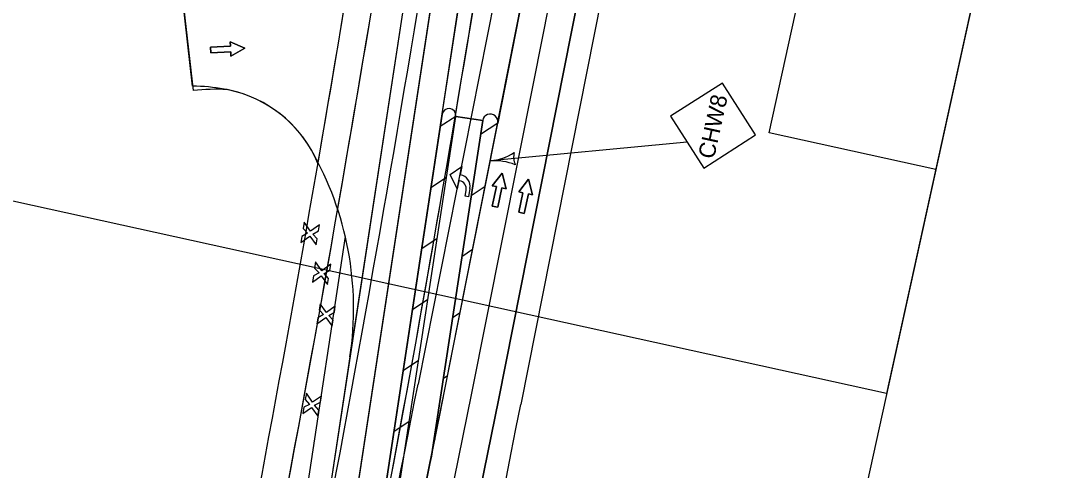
# Model space of a CAD drawing. Extents: x 14107086 to 14122011, y 8637163 to 8671583.
# Drawn here: x 14107764 to 14108216.1, y 8639702.8 to 8639900.3 of the extents above; entities that cross this region are included whole.
import ezdxf

# ---------------------------------------------------------------- set-up
doc = ezdxf.new("R2010")
doc.units = 0
for name, color, linetype in [('Cell', 7, 'Continuous'), ('dsn_stg_shd_prev', 7, 'Continuous'), ('dsnNonPlotable', 7, 'Continuous'), ('dsnPaintExistingChannelizingLaneYellow', 7, 'Continuous'), ('dsnPaintExistingEdgeLineRightWhite', 7, 'Continuous'), ('dsnPaintPlaceBrokenLaneWhite', 7, 'Continuous'), ('dsnPaintPlaceChannelizingLaneWhite', 7, 'Continuous'), ('dsnPaintPlaceChannelizingLaneYellow', 7, 'Continuous'), ('dsnPaintPlaceEdgeLineRightWhite', 7, 'Continuous'), ('dsnPaintRemoveDoubleCenterLineYellow', 7, 'Continuous'), ('dsnShadingPaved', 7, 'Continuous'), ('dsnStdLabel', 7, 'Continuous'), ('dsnTextOverlapEven', 7, 'Continuous'), ('Level 2', 7, 'Continuous'), ('Level 5', 7, 'Continuous')]:
    doc.layers.add(name, color=color, linetype=linetype)

msp = doc.modelspace()

# ---------------------------------------------------------------- linework, layer by layer
at = {"layer": 'Cell'}
for p, q in [((14107956.89, 8639829.91), (14107956.58, 8639829.95)), ((14107957.11, 8639832.53), (14107957.29, 8639832.5)), ((14107888.58, 8639811.69), (14107888.16, 8639808.97)), ((14107891.39, 8639807.83), (14107888.58, 8639811.69)), ((14107895.25, 8639810.65), (14107891.39, 8639807.83)), ((14107894.82, 8639807.93), (14107895.25, 8639810.65)), ((14107890.11, 8639806.9), (14107887.61, 8639805.52)), ((14107888.16, 8639808.97), (14107890.11, 8639806.9)), ((14107892.33, 8639806.55), (14107894.82, 8639807.93)), ((14107894.28, 8639804.47), (14107892.33, 8639806.55)), ((14107887.19, 8639802.8), (14107891.05, 8639805.61)), ((14107887.61, 8639805.52), (14107887.19, 8639802.8)), ((14107891.05, 8639805.61), (14107893.86, 8639801.76)), ((14107893.86, 8639801.76), (14107894.28, 8639804.47)), ((14107893.61, 8639794.31), (14107893.18, 8639791.59)), ((14107896.42, 8639790.45), (14107893.61, 8639794.31)), ((14107900.28, 8639793.26), (14107896.42, 8639790.45)), ((14107899.85, 8639790.55), (14107900.28, 8639793.26)), ((14107892.22, 8639785.42), (14107896.07, 8639788.23)), ((14107892.64, 8639788.13), (14107892.22, 8639785.42)), ((14107895.14, 8639789.51), (14107892.64, 8639788.13)), ((14107893.18, 8639791.59), (14107895.14, 8639789.51)), ((14107896.07, 8639788.23), (14107898.89, 8639784.37)), ((14107897.36, 8639789.16), (14107899.85, 8639790.55)), ((14107899.31, 8639787.09), (14107897.36, 8639789.16)), ((14107898.89, 8639784.37), (14107899.31, 8639787.09)), ((14107895.61, 8639775.98), (14107895.18, 8639773.26)), ((14107898.42, 8639772.12), (14107895.61, 8639775.98)), ((14107902.28, 8639774.93), (14107898.42, 8639772.12)), ((14107901.85, 8639772.22), (14107902.28, 8639774.93)), ((14107894.22, 8639767.09), (14107898.07, 8639769.9)), ((14107894.64, 8639769.8), (14107894.22, 8639767.09)), ((14107897.14, 8639771.18), (14107894.64, 8639769.8)), ((14107895.18, 8639773.26), (14107897.14, 8639771.18)), ((14107898.07, 8639769.9), (14107900.88, 8639766.04)), ((14107899.36, 8639770.84), (14107901.85, 8639772.22)), ((14107901.31, 8639768.76), (14107899.36, 8639770.84)), ((14107900.88, 8639766.04), (14107901.31, 8639768.76)), ((14107889.59, 8639736.62), (14107889.08, 8639733.92)), ((14107889.08, 8639733.92), (14107890.97, 8639731.78)), ((14107892.29, 8639732.68), (14107889.59, 8639736.62)), ((14107896.22, 8639735.38), (14107892.29, 8639732.68)), ((14107895.72, 8639732.68), (14107896.22, 8639735.38)), ((14107888.44, 8639730.48), (14107887.94, 8639727.77)), ((14107887.94, 8639727.77), (14107891.87, 8639730.47)), ((14107890.97, 8639731.78), (14107888.44, 8639730.48)), ((14107891.87, 8639730.47), (14107894.57, 8639726.54)), ((14107893.19, 8639731.37), (14107895.72, 8639732.68)), ((14107895.08, 8639729.24), (14107893.19, 8639731.37)), ((14107894.57, 8639726.54), (14107895.08, 8639729.24))]:
    msp.add_line(p, q, dxfattribs=at)
for points in [[(14107952.78, 8639832.67), (14107957.86, 8639836.14), (14107957.11, 8639832.53)], [(14107952.78, 8639832.67), (14107957.86, 8639836.14), (14107957.11, 8639832.53)], [(14107956.58, 8639829.95), (14107955.83, 8639826.35), (14107952.78, 8639832.67)], [(14107956.58, 8639829.95), (14107955.83, 8639826.35), (14107952.78, 8639832.67)], [(14107956.89, 8639829.91), (14107956.58, 8639829.95)], [(14107957.11, 8639832.53), (14107957.29, 8639832.5)], [(14107961.41, 8639826.54), (14107960.84, 8639822.91), (14107959.37, 8639823.14), (14107959.77, 8639825.73)], [(14107961.41, 8639826.54), (14107960.84, 8639822.91), (14107959.37, 8639823.14), (14107959.77, 8639825.73)]]:
    msp.add_lwpolyline(points, dxfattribs=at)
for centre, major_axis in [((14107956.32, 8639826.27), (-0.57, -3.64)), ((14107956.32, 8639826.27), (-0.57, -3.64)), ((14107956.49, 8639827.31), (-0.81, -5.19)), ((14107956.49, 8639827.31), (-0.81, -5.19))]:
    msp.add_ellipse(centre, major_axis=major_axis, ratio=0.9474, start_param=1.570796, end_param=3.141593, dxfattribs=at)
at = {"layer": 'dsn_stg_shd_prev'}
for p, q in [((14107993.19, 8640015.44), (14107938.65, 8639740.6)), ((14107993.19, 8640015.44), (14107938.65, 8639740.6)), ((14107950.42, 8639738.27), (14108004.96, 8640013.11)), ((14108038.31, 8640006.49), (14107983.77, 8639731.65)), ((14107950.42, 8639738.27), (14107992.68, 8639951.24)), ((14107833.76, 8639922), (14107839.82, 8639869.51))]:
    msp.add_line(p, q, dxfattribs=at)
for centre, radius, start, end in [((14098576.76, 8641447.78), 9456, 348.449343, 351.672846), ((14098576.76, 8641447.78), 9468, 347.807255, 351.672846), ((14098576.76, 8641447.78), 9468, 348.194582, 351.672846), ((14098576.76, 8641447.78), 9488, 348.202524, 351.672846), ((14098576.76, 8641447.78), 9488, 348.202524, 351.672846), ((14098576.76, 8641447.78), 9512, 348.176197, 351.653537), ((14098576.76, 8641447.78), 9512, 348.212012, 351.653537), ((14098576.76, 8641447.78), 9456, 350.195701, 351.23682), ((14107849.81, 8639782.85), 87.24, 86.7296, 96.5795), ((14107844.07, 8639816), 55, 23.1027, 78.7566), ((14089678.7, 8643364.11), 18628, 347.714933, 348.776036), ((14089678.7, 8643364.11), 18628, 347.714997, 348.776036), ((14089678.7, 8643364.11), 18616, 348.014807, 348.776036), ((14089678.7, 8643364.11), 18616, 348.014807, 348.776036), ((14089678.7, 8643364.11), 18662, 347.714933, 348.776036)]:
    msp.add_arc(centre, radius, start, end, dxfattribs=at)
at = {"layer": 'dsnNonPlotable'}
for points in [[(14107651.31, 8639844.94), (14107987.7, 8641375.92), (14108480.93, 8641267.54), (14108144.54, 8639736.56)], [(14107379.3, 8638606.97), (14107715.69, 8640137.95), (14108208.92, 8640029.57), (14107872.54, 8638498.6)]]:
    msp.add_lwpolyline(points, close=True, dxfattribs=at)
at = {"layer": 'dsnPaintExistingChannelizingLaneYellow'}
msp.add_line((14107949.23, 8639859.12), (14107909.09, 8639595.99), dxfattribs=at)
at = {"layer": 'dsnPaintExistingEdgeLineRightWhite'}
msp.add_line((14107908.71, 8639752.63), (14107885.37, 8639599.61), dxfattribs=at)
for centre, radius, start, end in [((14107838.11, 8639781.51), 90, 80.198, 89.1076), ((14107844.07, 8639816), 55, 29.809, 80.198), ((14107770.31, 8639773.74), 140, 351.326, 29.809)]:
    msp.add_arc(centre, radius, start, end, dxfattribs=at)
at = {"layer": 'dsnPaintPlaceBrokenLaneWhite'}
for points in [[(14107897.23, 8639597.8), (14107950.02, 8639943.8), (14107963.82, 8640034.39)], [(14107843.64, 8639178.29), (14107884.58, 8639364.66), (14107924.33, 8639550.11), (14107962.19, 8639735.96), (14107989.46, 8639873.37), (14108016.73, 8640010.77)]]:
    msp.add_lwpolyline(points, dxfattribs=at)
at = {"layer": 'dsnPaintPlaceChannelizingLaneWhite'}
for p, q in [((14107944.41, 8639708.12), (14107967.03, 8639856.41)), ((14107973.63, 8639855.23), (14107966.08, 8639850.19)), ((14107968.12, 8639827.49), (14107961.99, 8639823.39)), ((14107962.62, 8639799.75), (14107957.91, 8639796.59)), ((14107957.11, 8639772), (14107953.82, 8639769.8)), ((14107951.61, 8639744.26), (14107949.73, 8639743)), ((14107946.08, 8639716.5), (14107945.64, 8639716.21))]:
    msp.add_line(p, q, dxfattribs=at)
msp.add_lwpolyline([(14107944.41, 8639708.12), (14107950.42, 8639738.27), (14107973.63, 8639855.23)], dxfattribs=at)
msp.add_arc((14107970.34, 8639855.88), 3.35, 348.776, 171.0218, dxfattribs=at)
at = {"layer": 'dsnPaintPlaceChannelizingLaneYellow'}
for p, q in [((14107898.55, 8639487.12), (14107955.17, 8639858.22)), ((14107955.17, 8639858.22), (14107948.4, 8639853.69)), ((14107951.08, 8639831.42), (14107944.31, 8639826.9)), ((14107946.99, 8639804.63), (14107940.23, 8639800.1)), ((14107942.9, 8639777.83), (14107936.14, 8639773.31)), ((14107938.82, 8639751.04), (14107932.05, 8639746.51)), ((14107934.73, 8639724.24), (14107927.97, 8639719.72))]:
    msp.add_line(p, q, dxfattribs=at)
msp.add_arc((14107952.2, 8639858.67), 3, 351.326, 171.326, dxfattribs=at)
at = {"layer": 'dsnPaintPlaceEdgeLineRightWhite'}
msp.add_line((14107906.66, 8639805.51), (14107875.48, 8639601.12), dxfattribs=at)
msp.add_lwpolyline([(14107855.36, 8639175.71), (14107896.3, 8639362.11), (14107936.08, 8639547.66), (14107973.96, 8639733.6), (14108028.5, 8640008.43)], dxfattribs=at)
at = {"layer": 'dsnPaintRemoveDoubleCenterLineYellow'}
msp.add_line((14107897.23, 8639597.8), (14108002.8, 8640289.8), dxfattribs=at)
at = {"layer": 'dsnShadingPaved'}
for p, q in [((14107990.94, 8640291.61), (14107885.37, 8639599.61)), ((14107909.09, 8639595.99), (14108014.66, 8640287.99)), ((14108004.96, 8640013.11), (14107973.63, 8639855.23)), ((14107949.24, 8639859.12), (14107967.08, 8639976.1)), ((14107937.44, 8639940.91), (14107908.71, 8639752.63)), ((14107839.51, 8639871.5), (14107833.76, 8639922)), ((14107897.98, 8639483.38), (14107955.17, 8639858.22)), ((14107967.03, 8639856.41), (14107944.41, 8639708.12)), ((14107955.17, 8639858.22), (14107967.03, 8639856.41)), ((14107967.03, 8639856.41), (14107955.17, 8639858.22))]:
    msp.add_line(p, q, dxfattribs=at)
for points in [[(14107831.92, 8639180.86), (14107872.85, 8639367.2), (14107912.58, 8639552.57), (14107950.43, 8639738.33), (14108004.96, 8640013.11)], [(14108028.5, 8640008.43), (14107973.96, 8639733.6), (14107936.08, 8639547.66), (14107896.3, 8639362.11), (14107855.36, 8639175.71)], [(14107944.81, 8639710.74), (14107912.58, 8639552.57), (14107898.55, 8639487.12)]]:
    msp.add_lwpolyline(points, dxfattribs=at)
for centre, radius, start, end in [((14107838.11, 8639781.51), 90, 80.198, 89.1076), ((14107844.07, 8639816), 55, 29.809, 80.198), ((14107952.2, 8639858.67), 3, 351.326, 171.326), ((14107970.34, 8639855.88), 3.35, 348.776, 171.0218), ((14107770.31, 8639773.74), 140, 351.326, 29.809)]:
    msp.add_arc(centre, radius, start, end, dxfattribs=at)
at = {"layer": 'dsnStdLabel'}
msp.add_line((14108056.9, 8639846.89), (14107970.35, 8639838.62), dxfattribs=at)
msp.add_lwpolyline([(14108064.17, 8639835.52), (14108086.92, 8639850.07), (14108072.37, 8639872.81), (14108049.62, 8639858.26)], close=True, dxfattribs=at)
for centre, radius, start, end in [((14107968.16, 8639861.47), 22.95, 275.4595, 303.5307), ((14107989.5, 8639840.45), 8.86, 167.7253, 203.1938), ((14107972.53, 8639815.77), 22.95, 67.3883, 95.4596)]:
    msp.add_arc(centre, radius, start, end, dxfattribs=at)
at = {"layer": 'dsnTextOverlapEven'}
for points in [[(14108208.92, 8640029.57), (14108166.16, 8639834.94), (14108092.91, 8639851.03), (14108135.67, 8640045.67)], [(14108092.91, 8639851.03), (14108135.67, 8640045.67), (14108208.92, 8640029.57), (14108166.16, 8639834.94)]]:
    msp.add_lwpolyline(points, close=True, dxfattribs=at)
at = {"layer": 'Level 2'}
for points in [[(14107847.44, 8639888.53), (14107847.57, 8639886.03), (14107856.31, 8639886.5), (14107856.41, 8639884.62), (14107862.49, 8639888.08), (14107856.08, 8639890.86), (14107856.18, 8639888.99)], [(14107971.24, 8639818.81), (14107973.69, 8639818.29), (14107975.5, 8639826.85), (14107977.34, 8639826.46), (14107975.57, 8639833.22), (14107971.22, 8639827.76), (14107973.06, 8639827.37)], [(14107982.87, 8639816.15), (14107985.32, 8639815.63), (14107987.13, 8639824.19), (14107988.96, 8639823.8), (14107987.2, 8639830.57), (14107982.85, 8639825.1), (14107984.68, 8639824.71)]]:
    msp.add_lwpolyline(points, close=True, dxfattribs=at)
at = {"layer": 'Level 5'}
for points in [[(14107856.18, 8639888.99), (14107856.08, 8639890.86), (14107862.49, 8639888.08), (14107856.41, 8639884.62), (14107856.31, 8639886.5), (14107847.57, 8639886.03), (14107847.44, 8639888.53), (14107856.18, 8639888.99)], [(14107973.06, 8639827.37), (14107971.22, 8639827.76), (14107975.57, 8639833.22), (14107977.34, 8639826.46), (14107975.5, 8639826.85), (14107973.69, 8639818.29), (14107971.24, 8639818.81), (14107973.06, 8639827.37)], [(14107984.68, 8639824.71), (14107982.85, 8639825.1), (14107987.2, 8639830.57), (14107988.96, 8639823.8), (14107987.13, 8639824.19), (14107985.32, 8639815.63), (14107982.87, 8639816.15), (14107984.68, 8639824.71)]]:
    msp.add_lwpolyline(points, dxfattribs=at)

# ---------------------------------------------------------------- texts
at = {"layer": 'dsnStdLabel'}
msp.add_text('CHW8', height=7.2, rotation=77.6078, dxfattribs=at).set_placement((14108068.65, 8639839.15))

doc.saveas('drawing.dxf')
